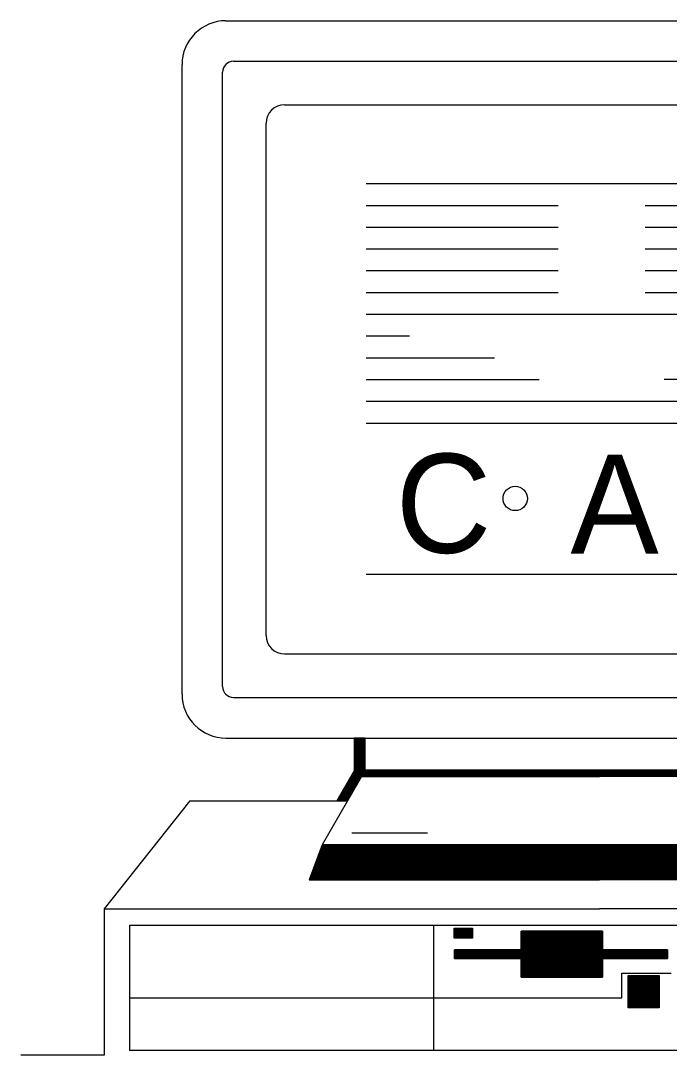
# Model space of a CAD drawing. Extents: x 0 to 53.3, y -0.3 to 37.1.
# Drawn here: x 41.133 to 42.432, y 1.925 to 3.997 of the extents above; entities that cross this region are included whole.
import ezdxf

# ---------------------------------------------------------------- set-up
doc = ezdxf.new("R2010")
doc.units = 0
for name, color, linetype in [('Level 1', 7, 'Continuous'), ('Level 25', 7, 'Continuous'), ('Level 50', 7, 'Continuous')]:
    doc.layers.add(name, color=color, linetype=linetype)

msp = doc.modelspace()

# ---------------------------------------------------------------- linework, layer by layer
at = {"layer": 'Level 1'}
for p, q in [((41.8253, 3.6705), (42.7686, 3.6705)), ((41.8253, 3.6269), (42.2098, 3.6269)), ((42.3839, 3.6269), (42.7686, 3.6269)), ((41.8253, 3.5834), (42.2098, 3.5834)), ((42.3839, 3.5834), (42.7686, 3.5834)), ((41.8253, 3.5399), (42.2098, 3.5399)), ((42.3839, 3.5399), (42.7686, 3.5399)), ((41.8253, 3.4962), (42.2098, 3.4962)), ((42.3839, 3.4962), (42.7686, 3.4962)), ((41.8253, 3.4525), (42.2098, 3.4525)), ((42.3839, 3.4525), (42.7686, 3.4525)), ((41.8253, 3.4089), (42.7686, 3.4089)), ((41.8253, 3.3655), (41.9124, 3.3655)), ((41.8253, 3.3219), (42.0823, 3.3219)), ((41.8253, 3.2784), (42.1716, 3.2784)), ((42.7684, 3.2784), (42.4221, 3.2784)), ((41.8253, 3.2347), (42.7686, 3.2347)), ((41.8253, 3.191), (42.7686, 3.191)), ((41.8253, 2.8885), (42.7703, 2.8885))]:
    msp.add_line(p, q, dxfattribs=at)
msp.add_circle((42.1238, 3.0399), 0.0244, dxfattribs=at)
at = {"layer": 'Level 25'}
for p, q in [((41.4566, 2.648), (41.4566, 3.9089)), ((41.5378, 2.6634), (41.5378, 3.8937)), ((41.6251, 2.7652), (41.6251, 3.7917)), ((41.6618, 2.7285), (42.9234, 2.7285)), ((41.5598, 2.6414), (43.0239, 2.6414)), ((41.5446, 2.56), (43.0406, 2.56)), ((41.8019, 2.4954), (41.8019, 2.56)), ((41.8019, 2.5595), (41.8231, 2.5595)), ((41.8019, 2.5582), (41.8231, 2.5582)), ((41.8019, 2.557), (41.8231, 2.557)), ((41.8019, 2.5555), (41.8231, 2.5555)), ((41.8019, 2.5542), (41.8231, 2.5542)), ((41.8019, 2.5529), (41.8231, 2.5529)), ((41.8019, 2.5517), (41.8231, 2.5517)), ((41.8019, 2.5504), (41.8231, 2.5504)), ((41.8231, 2.4954), (41.8231, 2.56)), ((41.8019, 2.5489), (41.8231, 2.5489)), ((41.8019, 2.5475), (41.8231, 2.5475)), ((41.8019, 2.5464), (41.8231, 2.5464)), ((41.8019, 2.545), (41.8231, 2.545)), ((41.8019, 2.5437), (41.8231, 2.5437)), ((41.8019, 2.5424), (41.8231, 2.5424)), ((41.8019, 2.541), (41.8231, 2.541)), ((41.8019, 2.5397), (41.8231, 2.5397)), ((41.8019, 2.5384), (41.8231, 2.5384)), ((41.8019, 2.5372), (41.8231, 2.5372)), ((41.8019, 2.5357), (41.8231, 2.5357)), ((41.8019, 2.5344), (41.8231, 2.5344)), ((41.8019, 2.5332), (41.8231, 2.5332)), ((41.8019, 2.5319), (41.8231, 2.5319)), ((41.8019, 2.5305), (41.8231, 2.5305)), ((41.8019, 2.529), (41.8231, 2.529)), ((41.8019, 2.5279), (41.8231, 2.5279)), ((41.8019, 2.5265), (41.8231, 2.5265)), ((41.8019, 2.5252), (41.8231, 2.5252)), ((41.8019, 2.524), (41.8231, 2.524)), ((41.8019, 2.5225), (41.8231, 2.5225)), ((41.8019, 2.5212), (41.8231, 2.5212)), ((41.8019, 2.5199), (41.8231, 2.5199)), ((41.8019, 2.5187), (41.8231, 2.5187)), ((41.8019, 2.5174), (41.8231, 2.5174)), ((41.8019, 2.5159), (41.8231, 2.5159)), ((41.8019, 2.5145), (41.8231, 2.5145)), ((41.8019, 2.5134), (41.8231, 2.5134)), ((41.8019, 2.512), (41.8231, 2.512)), ((41.8019, 2.5107), (41.8231, 2.5107)), ((41.8019, 2.5094), (41.8231, 2.5094)), ((41.8019, 2.508), (41.8231, 2.508)), ((41.8231, 2.4954), (41.7373, 2.3459)), ((41.8019, 2.4954), (41.7668, 2.4344)), ((41.7971, 2.4869), (41.8183, 2.4869)), ((41.7979, 2.4882), (41.8191, 2.4882)), ((41.7988, 2.4895), (41.8198, 2.4895)), ((41.7994, 2.491), (41.8204, 2.491)), ((41.8001, 2.4922), (41.8213, 2.4922)), ((41.8009, 2.4935), (41.8219, 2.4935)), ((41.8016, 2.4949), (41.8228, 2.4949)), ((41.8019, 2.5067), (41.8231, 2.5067)), ((41.8019, 2.5054), (41.8231, 2.5054)), ((41.8019, 2.5042), (41.8231, 2.5042)), ((41.8019, 2.5027), (41.8231, 2.5027)), ((41.8019, 2.5014), (41.8231, 2.5014)), ((41.8019, 2.5002), (41.8231, 2.5002)), ((41.8019, 2.4989), (41.8231, 2.4989)), ((41.8019, 2.4975), (41.8231, 2.4975)), ((41.8019, 2.496), (41.8231, 2.496)), ((41.8183, 2.487), (42.2926, 2.487)), ((41.8191, 2.4884), (42.2926, 2.4884)), ((41.8198, 2.4897), (42.2926, 2.4897)), ((41.8204, 2.491), (42.2926, 2.491)), ((41.8214, 2.4924), (42.2926, 2.4924)), ((41.8221, 2.4937), (42.2926, 2.4937)), ((41.8229, 2.495), (42.2926, 2.495)), ((41.8231, 2.4954), (42.2926, 2.4954)), ((42.7619, 2.4954), (42.2926, 2.4954)), ((42.7623, 2.495), (42.2926, 2.495)), ((42.7631, 2.4937), (42.2926, 2.4937)), ((42.7638, 2.4924), (42.2926, 2.4924)), ((42.7644, 2.491), (42.2926, 2.491)), ((42.7653, 2.4897), (42.2926, 2.4897)), ((42.7659, 2.4884), (42.2926, 2.4884)), ((42.7668, 2.487), (42.2926, 2.487)), ((41.7858, 2.4672), (41.8068, 2.4672)), ((41.7864, 2.4684), (41.8076, 2.4684)), ((41.7873, 2.4697), (41.8084, 2.4697)), ((41.7881, 2.4712), (41.8091, 2.4712)), ((41.7888, 2.4724), (41.8099, 2.4724)), ((41.7896, 2.4737), (41.8106, 2.4737)), ((41.7903, 2.475), (41.8113, 2.475)), ((41.7909, 2.4764), (41.8123, 2.4764)), ((41.7919, 2.4777), (41.8129, 2.4777)), ((41.7924, 2.479), (41.8138, 2.479)), ((41.7934, 2.4804), (41.8144, 2.4804)), ((41.7941, 2.4815), (41.8153, 2.4815)), ((41.7948, 2.4829), (41.8159, 2.4829)), ((41.7956, 2.4844), (41.8166, 2.4844)), ((41.7963, 2.4857), (41.8174, 2.4857)), ((41.8159, 2.4829), (42.2926, 2.4829)), ((41.8161, 2.483), (42.2926, 2.483)), ((41.8168, 2.4844), (42.2926, 2.4844)), ((41.8176, 2.4859), (42.2926, 2.4859)), ((42.7676, 2.4859), (42.2926, 2.4859)), ((42.7684, 2.4844), (42.2926, 2.4844)), ((42.7691, 2.483), (42.2926, 2.483)), ((42.7693, 2.4829), (42.2926, 2.4829)), ((41.7736, 2.446), (41.7946, 2.446)), ((41.7743, 2.4474), (41.7956, 2.4474)), ((41.7751, 2.4485), (41.7963, 2.4485)), ((41.7759, 2.4499), (41.7971, 2.4499)), ((41.7768, 2.4514), (41.7978, 2.4514)), ((41.7774, 2.4527), (41.7984, 2.4527)), ((41.7781, 2.4539), (41.7993, 2.4539)), ((41.7789, 2.4552), (41.7999, 2.4552)), ((41.7796, 2.4565), (41.8008, 2.4565)), ((41.7804, 2.458), (41.8016, 2.458)), ((41.7813, 2.4592), (41.8024, 2.4592)), ((41.7821, 2.4605), (41.8031, 2.4605)), ((41.7828, 2.4619), (41.8038, 2.4619)), ((41.7834, 2.463), (41.8046, 2.463)), ((41.7843, 2.4645), (41.8053, 2.4645)), ((41.7849, 2.4659), (41.8063, 2.4659)), ((41.4723, 2.4344), (41.3009, 2.2182)), ((41.7676, 2.4354), (41.7886, 2.4354)), ((41.7683, 2.4367), (41.7894, 2.4367)), ((41.7689, 2.4382), (41.7903, 2.4382)), ((41.7699, 2.4394), (41.7909, 2.4394)), ((41.7706, 2.4407), (41.7918, 2.4407)), ((41.7714, 2.442), (41.7924, 2.442)), ((41.7721, 2.4434), (41.7933, 2.4434)), ((41.7729, 2.4447), (41.7939, 2.4447)), ((41.7964, 2.3704), (41.9479, 2.3704)), ((41.7373, 2.3459), (41.7114, 2.2757)), ((41.7363, 2.3429), (42.2926, 2.3429)), ((41.7368, 2.344), (42.2926, 2.344)), ((41.7371, 2.3454), (42.2926, 2.3454)), ((42.8479, 2.3454), (42.2926, 2.3454)), ((42.8484, 2.344), (42.2926, 2.344)), ((42.8491, 2.3429), (42.2926, 2.3429)), ((41.7283, 2.3215), (42.2926, 2.3215)), ((41.7289, 2.323), (42.2926, 2.323)), ((41.7294, 2.3244), (42.2926, 2.3244)), ((41.7298, 2.3255), (42.2926, 2.3255)), ((41.7303, 2.3269), (42.2926, 2.3269)), ((41.7309, 2.3282), (42.2926, 2.3282)), ((41.7313, 2.3297), (42.2926, 2.3297)), ((41.7318, 2.3309), (42.2926, 2.3309)), ((41.7323, 2.3322), (42.2926, 2.3322)), ((41.7328, 2.3335), (42.2926, 2.3335)), ((41.7333, 2.3347), (42.2926, 2.3347)), ((41.7338, 2.3362), (42.2926, 2.3362)), ((41.7341, 2.3375), (42.2926, 2.3375)), ((41.7348, 2.3389), (42.2926, 2.3389)), ((41.7353, 2.34), (42.2926, 2.34)), ((41.7356, 2.3414), (42.2926, 2.3414)), ((42.8494, 2.3414), (42.2926, 2.3414)), ((42.8499, 2.34), (42.2926, 2.34)), ((42.8504, 2.3389), (42.2926, 2.3389)), ((42.8509, 2.3375), (42.2926, 2.3375)), ((42.8514, 2.3362), (42.2926, 2.3362)), ((42.8518, 2.3347), (42.2926, 2.3347)), ((42.8523, 2.3335), (42.2926, 2.3335)), ((42.8529, 2.3322), (42.2926, 2.3322)), ((42.8534, 2.3309), (42.2926, 2.3309)), ((42.8538, 2.3297), (42.2926, 2.3297)), ((42.8543, 2.3282), (42.2926, 2.3282)), ((42.8549, 2.3269), (42.2926, 2.3269)), ((42.8553, 2.3255), (42.2926, 2.3255)), ((42.8558, 2.3244), (42.2926, 2.3244)), ((42.8561, 2.323), (42.2926, 2.323)), ((42.8568, 2.3215), (42.2926, 2.3215)), ((41.7206, 2.3005), (42.2926, 2.3005)), ((41.7209, 2.3017), (42.2926, 2.3017)), ((41.7216, 2.3032), (42.2926, 2.3032)), ((41.7221, 2.3045), (42.2926, 2.3045)), ((41.7226, 2.3059), (42.2926, 2.3059)), ((41.7229, 2.307), (42.2926, 2.307)), ((41.7236, 2.3084), (42.2926, 2.3084)), ((41.7239, 2.3099), (42.2926, 2.3099)), ((41.7244, 2.311), (42.2926, 2.311)), ((41.7249, 2.3124), (42.2926, 2.3124)), ((41.7254, 2.3137), (42.2926, 2.3137)), ((41.7259, 2.315), (42.2926, 2.315)), ((41.7264, 2.3164), (42.2926, 2.3164)), ((41.7268, 2.3177), (42.2926, 2.3177)), ((41.7274, 2.319), (42.2926, 2.319)), ((41.7279, 2.3202), (42.2926, 2.3202)), ((42.8573, 2.3202), (42.2926, 2.3202)), ((42.8578, 2.319), (42.2926, 2.319)), ((42.8583, 2.3177), (42.2926, 2.3177)), ((42.8588, 2.3164), (42.2926, 2.3164)), ((42.8591, 2.315), (42.2926, 2.315)), ((42.8596, 2.3137), (42.2926, 2.3137)), ((42.8603, 2.3124), (42.2926, 2.3124)), ((42.8606, 2.311), (42.2926, 2.311)), ((42.8611, 2.3099), (42.2926, 2.3099)), ((42.8616, 2.3084), (42.2926, 2.3084)), ((42.8623, 2.307), (42.2926, 2.307)), ((42.8626, 2.3059), (42.2926, 2.3059)), ((42.8631, 2.3045), (42.2926, 2.3045)), ((42.8634, 2.3032), (42.2926, 2.3032)), ((42.8641, 2.3017), (42.2926, 2.3017)), ((42.8646, 2.3005), (42.2926, 2.3005)), ((41.7133, 2.2807), (42.2926, 2.2807)), ((41.7138, 2.282), (42.2926, 2.282)), ((41.7143, 2.2834), (42.2926, 2.2834)), ((41.7148, 2.2847), (42.2926, 2.2847)), ((41.7151, 2.286), (42.2926, 2.286)), ((41.7156, 2.2872), (42.2926, 2.2872)), ((41.7163, 2.2885), (42.2926, 2.2885)), ((41.7166, 2.29), (42.2926, 2.29)), ((41.7171, 2.2914), (42.2926, 2.2914)), ((41.7176, 2.2925), (42.2926, 2.2925)), ((41.7183, 2.2939), (42.2926, 2.2939)), ((41.7186, 2.2952), (42.2926, 2.2952)), ((41.7191, 2.2967), (42.2926, 2.2967)), ((41.7194, 2.2979), (42.2926, 2.2979)), ((41.7201, 2.2992), (42.2926, 2.2992)), ((42.8649, 2.2992), (42.2926, 2.2992)), ((42.8656, 2.2979), (42.2926, 2.2979)), ((42.8661, 2.2967), (42.2926, 2.2967)), ((42.8664, 2.2952), (42.2926, 2.2952)), ((42.8669, 2.2939), (42.2926, 2.2939)), ((42.8676, 2.2925), (42.2926, 2.2925)), ((42.8679, 2.2914), (42.2926, 2.2914)), ((42.8684, 2.29), (42.2926, 2.29)), ((42.8689, 2.2885), (42.2926, 2.2885)), ((42.8694, 2.2872), (42.2926, 2.2872)), ((42.8699, 2.286), (42.2926, 2.286)), ((42.8704, 2.2847), (42.2926, 2.2847)), ((42.8708, 2.2834), (42.2926, 2.2834)), ((42.8714, 2.282), (42.2926, 2.282)), ((42.8719, 2.2807), (42.2926, 2.2807)), ((41.7118, 2.2769), (42.2926, 2.2769)), ((41.7121, 2.278), (42.2926, 2.278)), ((41.7128, 2.2794), (42.2926, 2.2794)), ((42.8723, 2.2794), (42.2926, 2.2794)), ((42.8729, 2.278), (42.2926, 2.278)), ((42.8734, 2.2769), (42.2926, 2.2769)), ((41.3009, 2.2182), (41.3009, 1.9245)), ((41.3009, 2.2182), (42.2926, 2.2182)), ((43.2841, 2.2182), (42.2926, 2.2182)), ((41.9606, 1.9342), (41.9606, 2.185)), ((42.0014, 2.1794), (42.0384, 2.1794)), ((42.0014, 2.178), (42.0384, 2.178)), ((42.0014, 2.1765), (42.0384, 2.1765)), ((42.0014, 2.1752), (42.0384, 2.1752)), ((42.0014, 2.174), (42.0384, 2.174)), ((42.0014, 2.1727), (42.0384, 2.1727)), ((42.0014, 2.1714), (42.0384, 2.1714)), ((42.0014, 2.1699), (42.0384, 2.1699)), ((42.0014, 2.1687), (42.0384, 2.1687)), ((42.0014, 2.1674), (42.0384, 2.1674)), ((42.0014, 2.166), (42.0384, 2.166)), ((42.0014, 2.1649), (42.0384, 2.1649)), ((42.0014, 2.1634), (42.0384, 2.1634)), ((42.0014, 2.162), (42.0384, 2.162)), ((42.0014, 2.1607), (42.0384, 2.1607)), ((42.0014, 2.1595), (42.0384, 2.1595)), ((42.1358, 2.173), (42.2986, 2.173)), ((42.1358, 2.1715), (42.2986, 2.1715)), ((42.1358, 2.1704), (42.2986, 2.1704)), ((42.1358, 2.169), (42.2986, 2.169)), ((42.1358, 2.1677), (42.2986, 2.1677)), ((42.1358, 2.1665), (42.2986, 2.1665)), ((42.1358, 2.165), (42.2986, 2.165)), ((42.1358, 2.1637), (42.2986, 2.1637)), ((42.1358, 2.1624), (42.2986, 2.1624)), ((42.1358, 2.1612), (42.2986, 2.1612)), ((42.1358, 2.1599), (42.2986, 2.1599)), ((42.1358, 2.1584), (42.2986, 2.1584)), ((42.1358, 2.157), (42.2986, 2.157)), ((42.1358, 2.1559), (42.2986, 2.1559)), ((42.0019, 2.1347), (42.4288, 2.1347)), ((42.1358, 2.1545), (42.2986, 2.1545)), ((42.1358, 2.1532), (42.2986, 2.1532)), ((42.1358, 2.1519), (42.2986, 2.1519)), ((42.1358, 2.1505), (42.2986, 2.1505)), ((42.1358, 2.1492), (42.2986, 2.1492)), ((42.1358, 2.1479), (42.2986, 2.1479)), ((42.1358, 2.1467), (42.2986, 2.1467)), ((42.1358, 2.1452), (42.2986, 2.1452)), ((42.1358, 2.1439), (42.2986, 2.1439)), ((42.1358, 2.1427), (42.2986, 2.1427)), ((42.1358, 2.1414), (42.2986, 2.1414)), ((42.1358, 2.14), (42.2986, 2.14)), ((42.1358, 2.1385), (42.2986, 2.1385)), ((42.1358, 2.1374), (42.2986, 2.1374)), ((42.1358, 2.136), (42.2986, 2.136)), ((42.0019, 2.1335), (42.4288, 2.1335)), ((42.0019, 2.132), (42.4288, 2.132)), ((42.0019, 2.1307), (42.4288, 2.1307)), ((42.0019, 2.1294), (42.4288, 2.1294)), ((42.0019, 2.1282), (42.4288, 2.1282)), ((42.0019, 2.1269), (42.4288, 2.1269)), ((42.0019, 2.1254), (42.4288, 2.1254)), ((42.0019, 2.124), (42.4288, 2.124)), ((42.0019, 2.1229), (42.4288, 2.1229)), ((42.0019, 2.1215), (42.4288, 2.1215)), ((42.0019, 2.1202), (42.4288, 2.1202)), ((42.0019, 2.1189), (42.4288, 2.1189)), ((42.1358, 2.1175), (42.2986, 2.1175)), ((42.1358, 2.1162), (42.2986, 2.1162)), ((42.1358, 2.1149), (42.2986, 2.1149)), ((42.1358, 2.1137), (42.2986, 2.1137)), ((42.1358, 2.1122), (42.2986, 2.1122)), ((42.1358, 2.1109), (42.2986, 2.1109)), ((42.1358, 2.1097), (42.2986, 2.1097)), ((42.1358, 2.1084), (42.2986, 2.1084)), ((42.1358, 2.107), (42.2986, 2.107)), ((42.1358, 2.1055), (42.2986, 2.1055)), ((42.1358, 2.1044), (42.2986, 2.1044)), ((42.1358, 2.103), (42.2986, 2.103)), ((42.1358, 2.1017), (42.2986, 2.1017)), ((42.1358, 2.1005), (42.2986, 2.1005)), ((42.1358, 2.099), (42.2986, 2.099)), ((42.1358, 2.0977), (42.2986, 2.0977)), ((42.1358, 2.0964), (42.2986, 2.0964)), ((42.1358, 2.0952), (42.2986, 2.0952)), ((42.1358, 2.0939), (42.2986, 2.0939)), ((42.1358, 2.0924), (42.2986, 2.0924)), ((42.1358, 2.091), (42.2986, 2.091)), ((42.1358, 2.0899), (42.2986, 2.0899)), ((42.1358, 2.0885), (42.2986, 2.0885)), ((42.1358, 2.0872), (42.2986, 2.0872)), ((42.1358, 2.0859), (42.2986, 2.0859)), ((42.1358, 2.0845), (42.2986, 2.0845)), ((42.1358, 2.0832), (42.2986, 2.0832)), ((42.1358, 2.0819), (42.2986, 2.0819)), ((42.3373, 2.0892), (42.4361, 2.0892)), ((42.3373, 2.0397), (42.3373, 2.0892)), ((42.3498, 2.0832), (42.4119, 2.0832)), ((42.3498, 2.0819), (42.4119, 2.0819)), ((42.3498, 2.0807), (42.4119, 2.0807)), ((42.3498, 2.0794), (42.4119, 2.0794)), ((42.3498, 2.0779), (42.4119, 2.0779)), ((42.3498, 2.0767), (42.4119, 2.0767)), ((42.3498, 2.0754), (42.4119, 2.0754)), ((42.3498, 2.074), (42.4119, 2.074)), ((42.3498, 2.0727), (42.4119, 2.0727)), ((42.3498, 2.0714), (42.4119, 2.0714)), ((42.3498, 2.07), (42.4119, 2.07)), ((42.3498, 2.0687), (42.4119, 2.0687)), ((42.3498, 2.0675), (42.4119, 2.0675)), ((42.3498, 2.0662), (42.4119, 2.0662)), ((42.3498, 2.0647), (42.4119, 2.0647)), ((42.3498, 2.0634), (42.4119, 2.0634)), ((42.3498, 2.0622), (42.4119, 2.0622)), ((42.3498, 2.0609), (42.4119, 2.0609)), ((42.3498, 2.0595), (42.4119, 2.0595)), ((42.3498, 2.058), (42.4119, 2.058)), ((42.3498, 2.0569), (42.4119, 2.0569)), ((42.3498, 2.0555), (42.4119, 2.0555)), ((42.3498, 2.0542), (42.4119, 2.0542)), ((42.3498, 2.053), (42.4119, 2.053)), ((41.3521, 2.0397), (42.3373, 2.0397)), ((42.3498, 2.0515), (42.4119, 2.0515)), ((42.3498, 2.0502), (42.4119, 2.0502)), ((42.3498, 2.0489), (42.4119, 2.0489)), ((42.3498, 2.0477), (42.4119, 2.0477)), ((42.3498, 2.0464), (42.4119, 2.0464)), ((42.3498, 2.0449), (42.4119, 2.0449)), ((42.3498, 2.0437), (42.4119, 2.0437)), ((42.3498, 2.0424), (42.4119, 2.0424)), ((42.3498, 2.041), (42.4119, 2.041)), ((42.3498, 2.0397), (42.4119, 2.0397)), ((42.3498, 2.0384), (42.4119, 2.0384)), ((42.3498, 2.037), (42.4119, 2.037)), ((42.3498, 2.0357), (42.4119, 2.0357)), ((42.3498, 2.0345), (42.4119, 2.0345)), ((42.3498, 2.0332), (42.4119, 2.0332)), ((42.3498, 2.0317), (42.4119, 2.0317)), ((42.3498, 2.0304), (42.4119, 2.0304)), ((42.3498, 2.0292), (42.4119, 2.0292)), ((42.3498, 2.0279), (42.4119, 2.0279)), ((42.3498, 2.0265), (42.4119, 2.0265)), ((42.3498, 2.025), (42.4119, 2.025)), ((42.3498, 2.0239), (42.4119, 2.0239)), ((42.3498, 2.0225), (42.4119, 2.0225)), ((42.3498, 2.0212), (42.4119, 2.0212)), ((42.3498, 2.02), (42.4119, 2.02)), ((41.3009, 1.9245), (41.1334, 1.9245))]:
    msp.add_line(p, q, dxfattribs=at)
for points in [[(41.8019, 2.56), (41.8019, 2.4954), (41.7668, 2.4344), (41.7881, 2.4344), (41.8231, 2.4954), (41.8231, 2.56)], [(41.8231, 2.4954), (41.8159, 2.4829), (42.2926, 2.4829), (42.2926, 2.4954)], [(42.7619, 2.4954), (42.7693, 2.4829), (42.2926, 2.4829), (42.2926, 2.4954)], [(41.7373, 2.3459), (41.7114, 2.2757), (42.2926, 2.2757), (42.2926, 2.3459)], [(42.8478, 2.3459), (42.8738, 2.2757), (42.2926, 2.2757), (42.2926, 2.3459)], [(41.3521, 2.185), (43.2361, 2.185), (43.2361, 1.9342), (41.3521, 1.9342)], [(42.0014, 2.1795), (42.0384, 2.1795), (42.0384, 2.1589), (42.0014, 2.1589)], [(42.1358, 2.1732), (42.1358, 2.1357), (42.0019, 2.1357), (42.0019, 2.1184), (42.1358, 2.1184), (42.1358, 2.081), (42.2986, 2.081), (42.2986, 2.1184), (42.4288, 2.1184), (42.4288, 2.1357), (42.2986, 2.1357), (42.2986, 2.1732)], [(42.3498, 2.0842), (42.4119, 2.0842), (42.4119, 2.0195), (42.3498, 2.0195)]]:
    msp.add_lwpolyline(points, close=True, dxfattribs=at)
for points in [[(42.1358, 2.1357), (42.1358, 2.1732), (42.2986, 2.1732), (42.2986, 2.1357)], [(42.1358, 2.1184), (42.0019, 2.1184), (42.0019, 2.1357), (42.1358, 2.1357)], [(42.2986, 2.1357), (42.4288, 2.1357), (42.4288, 2.1184), (42.2986, 2.1184)], [(42.2986, 2.1184), (42.2986, 2.081), (42.1358, 2.081), (42.1358, 2.1184)]]:
    msp.add_lwpolyline(points, dxfattribs=at)
for centre, start, end in [((41.5597, 3.8936), 90, 180), ((41.5597, 2.6632), 180, 270)]:
    msp.add_arc(centre, 0.022, start, end, dxfattribs=at)
at = {"layer": 'Level 50'}
for p, q in [((41.5446, 3.9969), (43.0406, 3.9969)), ((41.5598, 3.9157), (43.0239, 3.9157)), ((41.6618, 3.8284), (42.9234, 3.8284)), ((41.4723, 2.4344), (41.7881, 2.4344)), ((41.7373, 2.3459), (42.2926, 2.3459)), ((42.8478, 2.3459), (42.2926, 2.3459)), ((41.7114, 2.2757), (42.2926, 2.2757)), ((42.8738, 2.2757), (42.2926, 2.2757))]:
    msp.add_line(p, q, dxfattribs=at)
for centre, radius, start, end in [((41.5445, 3.9088), 0.088, 90, 180), ((41.6617, 3.7916), 0.0367, 90, 180), ((41.6617, 2.7652), 0.0367, 180, 270), ((41.5445, 2.648), 0.088, 180, 270)]:
    msp.add_arc(centre, radius, start, end, dxfattribs=at)

# ---------------------------------------------------------------- texts
at = {"layer": 'Level 1'}
for s, p in [('C', (41.8844, 2.931)), ('A', (42.2344, 2.9294))]:
    msp.add_text(s, height=0.1984, dxfattribs=at).set_placement(p)

doc.saveas('drawing.dxf')
